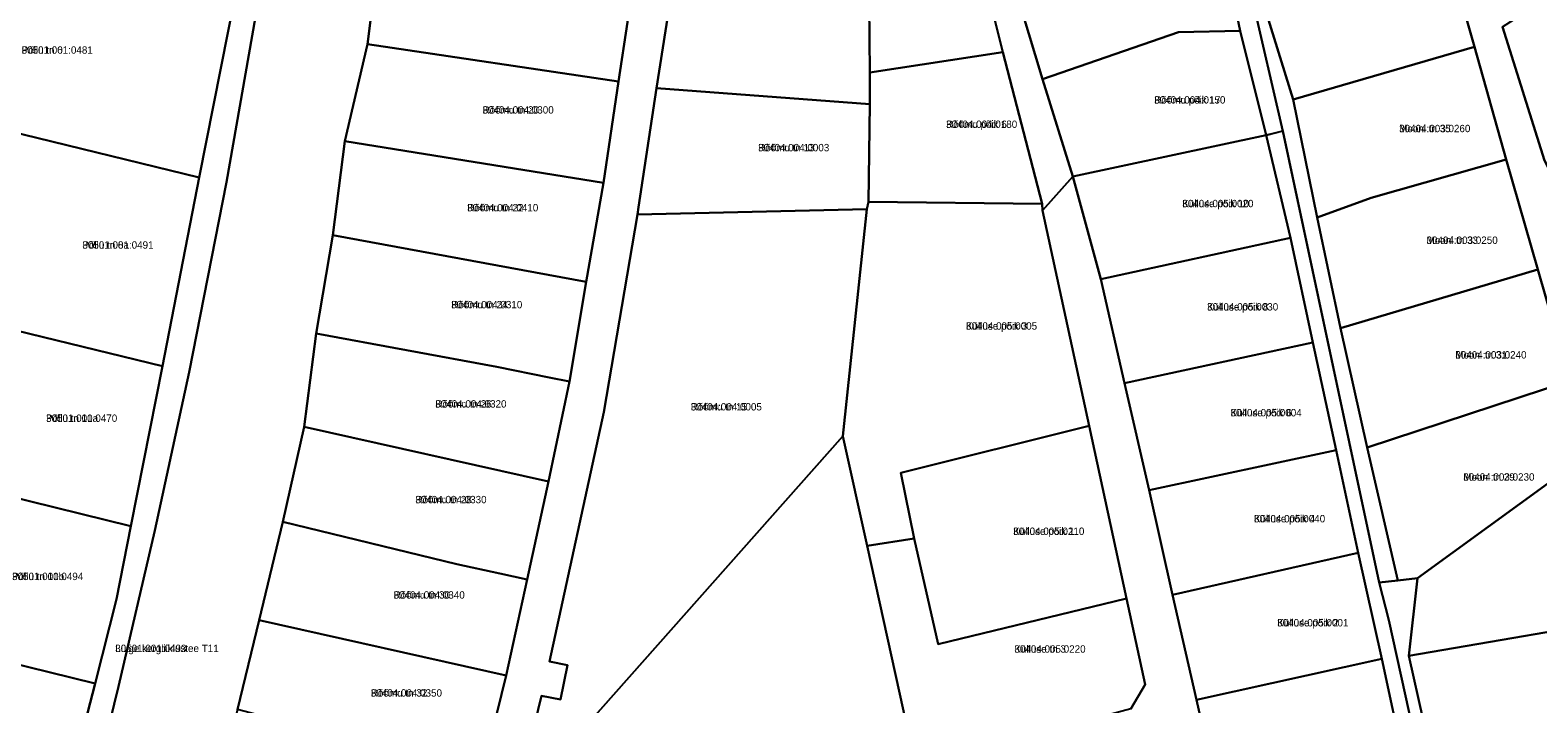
# Model space of a CAD drawing. Extents: x 542681 to 554572, y 6566489 to 6580482.
# Drawn here: x 543956.1 to 544263.2, y 6577115.7 to 6577252.9 of the extents above; entities that cross this region are included whole.
import ezdxf

# ---------------------------------------------------------------- set-up
doc = ezdxf.new("R2010")
doc.units = 0
for name, color, linetype in [('L_AADRESS', 7, 'Continuous'), ('PIIR', 7, 'Continuous'), ('TUNNUS', 7, 'Continuous')]:
    doc.layers.add(name, color=color, linetype=linetype)

msp = doc.modelspace()

# ---------------------------------------------------------------- linework, layer by layer
at = {"layer": 'PIIR'}
for points in [[(543807.92, 6576662.98), (543904.97, 6576885.47), (543907.57, 6576895.31), (543910.99, 6576906.44), (543922.56, 6576941.94), (543936.45, 6576984.61), (543948.61, 6577021.3), (543957.88, 6577054.74), (543966.17, 6577087.14), (543974.03, 6577119.2), (543981.47, 6577151), (543988.44, 6577183.28), (543996.05, 6577221.97), (544002.64, 6577259.57), (544005.96, 6577279.79), (544014.14, 6577348.31), (544016.62, 6577369.15), (544023.92, 6577429.37), (544023.1, 6577434.48), (544025.4, 6577449.01), (544027.21, 6577460.39), (544030.15, 6577550.17)], [(543952.91, 6577055.9), (543961.04, 6577087.76), (543969.28, 6577119.84), (543973.68, 6577136.98), (543976.6, 6577151.88), (543983, 6577184.45), (543990.52, 6577222.87), (543997.84, 6577259.95), (544004.56, 6577302.46), (544005.14, 6577308.18), (544009.28, 6577348.44), (544014.14, 6577348.31), (544005.96, 6577279.79), (544002.64, 6577259.57), (543996.05, 6577221.97), (543988.44, 6577183.28), (543981.47, 6577151), (543974.03, 6577119.2), (543966.17, 6577087.14), (543957.88, 6577054.74), (543948.61, 6577021.3)], [(544343.79, 6577266.92), (544323.61, 6577250.29), (544302.31, 6577236.4), (544281.19, 6577222.69), (544268.33, 6577214.08), (544276.94, 6577176.9), (544280.28, 6577170.48), (544273.95, 6577166.88), (544269.75, 6577181.48), (544263.2, 6577204.14), (544256.79, 6577226.59), (544250.31, 6577249.52), (544239.96, 6577285.6)], [(544152.26, 6577276.33), (544162.33, 6577242.91), (544168.46, 6577223.13), (544162.32, 6577216.19), (544162.21, 6577217.56), (544154.25, 6577248.45), (544146.15, 6577280.82)], [(544088.25, 6577270.53), (544083.69, 6577241.1), (544080.02, 6577216.88), (544079.79, 6577215.37), (544072.96, 6577175.07), (544061.83, 6577124.3), (544065.5, 6577123.55), (544064.08, 6577116.57), (544060.25, 6577117.34), (544054.74, 6577094.79), (544043.36, 6577081.91), (544048.15, 6577101.6), (544053.03, 6577121.49), (544057.31, 6577141.01), (544061.68, 6577160.97), (544065.91, 6577181.35), (544069.36, 6577201.67), (544072.86, 6577221.8), (544075.94, 6577242.44), (544079.61, 6577266.72)], [(544026.68, 6577265.1), (544024.78, 6577250.04), (544020.16, 6577230.32), (544017.69, 6577211.17), (544014.34, 6577191.11), (544011.89, 6577172.09), (544007.52, 6577152.78), (544002.68, 6577132.74), (543998.32, 6577114.57), (543993.36, 6577094.76), (543988.42, 6577075.56), (543983.52, 6577056.39), (543982.26, 6577052.27), (543976.84, 6577032.94), (543971.38, 6577015.47), (543965.45, 6576996.6), (543959.41, 6576977.68), (543956.86, 6576974.93), (543952, 6576959.13)], [(544204.94, 6577259.69), (544211.25, 6577232.37), (544207.86, 6577231.5), (544202.58, 6577252.78), (544201.13, 6577259.66)], [(544207.14, 6577258.94), (544213.36, 6577238.8), (544218.26, 6577214.74), (544223, 6577192.18), (544228.43, 6577167.92), (544234.67, 6577140.84), (544230.87, 6577140.38), (544211.25, 6577232.37), (544204.94, 6577259.69)], [(544256.03, 6577253.6), (544264.6, 6577226.38), (544266.26, 6577223.12), (544269.36, 6577223.2), (544293.74, 6577239.41), (544316.1, 6577253.81)], [(544236, 6577103.69), (544231.41, 6577124.89), (544226.64, 6577146.42), (544222.15, 6577167.37), (544217.35, 6577189.29), (544212.86, 6577210.6), (544207.86, 6577231.5), (544211.25, 6577232.38), (544230.87, 6577140.38), (544232.86, 6577132.75), (544263.5, 6576993.69)], [(544180.29, 6577114.66), (544183.2, 6577119.62), (544179.44, 6577137.12), (544171.81, 6577172.35), (544162.32, 6577216.19), (544168.46, 6577223.13), (544174.21, 6577202.2), (544179.04, 6577181.02), (544184, 6577159.2), (544188.81, 6577137.92), (544193.67, 6577116.5), (544198.52, 6577095.28)], [(544054.74, 6577094.79), (544121.6, 6577170.23), (544126.55, 6577147.86), (544136.48, 6577102.88)], [(544263.5, 6576993.69), (544232.86, 6577132.75), (544230.87, 6577140.38), (544234.67, 6577140.84), (544238.7, 6577141.31), (544236.96, 6577125.44), (544242.8, 6577099.39), (544248.72, 6577072.99), (544253.92, 6577049.8), (544259.33, 6577025.66), (544266.36, 6576994.23)]]:
    msp.add_lwpolyline(points, dxfattribs=at)
for points in [[(544127.01, 6577258.11), (544127.37, 6577286.93), (544146.15, 6577280.82), (544154.25, 6577248.45), (544127.12, 6577244.26)], [(544207.14, 6577258.94), (544239.96, 6577285.6), (544250.31, 6577249.52), (544213.36, 6577238.8)], [(544152.26, 6577276.33), (544201.13, 6577259.66), (544202.58, 6577252.78), (544190.01, 6577252.52), (544162.33, 6577242.91)], [(543915.25, 6577241.33), (543905.31, 6577273.35), (543961.72, 6577265.1), (543997.84, 6577259.95), (543990.52, 6577222.87), (543951.6, 6577232.38), (543945.76, 6577233.79)], [(544088.25, 6577270.53), (544127.01, 6577258.11), (544127.12, 6577244.26), (544127.14, 6577237.81), (544083.69, 6577241.1)], [(544026.68, 6577265.1), (544079.61, 6577266.72), (544075.94, 6577242.44), (544024.78, 6577250.04)], [(544266.26, 6577223.12), (544264.6, 6577226.38), (544256.03, 6577253.6), (544274.81, 6577265.67), (544293.74, 6577239.41), (544269.36, 6577223.2)], [(544162.33, 6577242.91), (544190.01, 6577252.52), (544202.58, 6577252.78), (544207.86, 6577231.5), (544168.46, 6577223.13)], [(544020.16, 6577230.32), (544024.78, 6577250.04), (544075.94, 6577242.44), (544072.86, 6577221.8)], [(544218.26, 6577214.74), (544213.36, 6577238.8), (544250.31, 6577249.52), (544256.79, 6577226.59), (544229.27, 6577218.74)], [(544127.14, 6577237.81), (544127.12, 6577244.26), (544154.25, 6577248.45), (544162.21, 6577217.56), (544126.82, 6577217.97)], [(544083.69, 6577241.1), (544127.14, 6577237.81), (544126.82, 6577217.97), (544126.52, 6577216.45), (544079.79, 6577215.37), (544080.02, 6577216.88)], [(543942.27, 6577194.39), (543951.6, 6577232.38), (543990.52, 6577222.87), (543983, 6577184.45)], [(544168.46, 6577223.13), (544207.86, 6577231.5), (544212.86, 6577210.6), (544174.21, 6577202.2)], [(544072.86, 6577221.8), (544069.36, 6577201.67), (544017.69, 6577211.17), (544020.16, 6577230.32)], [(544218.26, 6577214.74), (544229.27, 6577218.74), (544256.79, 6577226.59), (544263.2, 6577204.14), (544223, 6577192.18)], [(544079.79, 6577215.37), (544126.52, 6577216.45), (544121.6, 6577170.23), (544054.74, 6577094.79), (544060.25, 6577117.34), (544064.08, 6577116.57), (544065.5, 6577123.55), (544061.83, 6577124.3), (544072.96, 6577175.07)], [(544126.82, 6577217.97), (544162.21, 6577217.56), (544162.32, 6577216.19), (544171.81, 6577172.35), (544133.41, 6577162.76), (544136.18, 6577149.35), (544126.55, 6577147.86), (544121.6, 6577170.23), (544126.52, 6577216.45)], [(544017.69, 6577211.17), (544069.36, 6577201.67), (544065.91, 6577181.35), (544061.79, 6577182.18), (544051.13, 6577184.34), (544014.34, 6577191.11)], [(544174.21, 6577202.2), (544212.86, 6577210.6), (544217.35, 6577189.29), (544179.04, 6577181.02)], [(544223, 6577192.18), (544263.2, 6577204.14), (544269.75, 6577181.48), (544228.43, 6577167.92)], [(543935.49, 6577161.97), (543942.27, 6577194.39), (543983, 6577184.45), (543976.6, 6577151.88)], [(544014.34, 6577191.11), (544051.13, 6577184.34), (544061.79, 6577182.18), (544065.91, 6577181.35), (544061.68, 6577160.97), (544011.89, 6577172.09)], [(544179.04, 6577181.02), (544217.35, 6577189.29), (544222.15, 6577167.37), (544184, 6577159.2)], [(544234.67, 6577140.84), (544228.43, 6577167.92), (544269.75, 6577181.48), (544273.95, 6577166.88), (544238.7, 6577141.31)], [(544171.81, 6577172.35), (544179.44, 6577137.12), (544141.07, 6577127.85), (544136.18, 6577149.35), (544133.41, 6577162.76)], [(544011.89, 6577172.09), (544061.68, 6577160.97), (544057.31, 6577141.01), (544051.77, 6577142.22), (544042.97, 6577144.13), (544007.52, 6577152.78)], [(544184, 6577159.2), (544222.15, 6577167.37), (544226.64, 6577146.42), (544188.81, 6577137.92)], [(544238.7, 6577141.31), (544273.95, 6577166.88), (544286.02, 6577133.9), (544236.96, 6577125.44)], [(543927.62, 6577130.07), (543935.49, 6577161.97), (543976.6, 6577151.88), (543973.68, 6577136.98), (543969.28, 6577119.84)], [(544007.52, 6577152.78), (544042.97, 6577144.13), (544051.77, 6577142.22), (544057.31, 6577141.01), (544053.03, 6577121.49), (544002.68, 6577132.74)], [(544136.18, 6577149.35), (544141.07, 6577127.85), (544179.44, 6577137.12), (544183.2, 6577119.62), (544180.29, 6577114.66), (544136.48, 6577102.88), (544126.55, 6577147.86)], [(544188.81, 6577137.92), (544226.64, 6577146.42), (544231.41, 6577124.89), (544193.67, 6577116.5)], [(544018.49, 6577109.27), (543998.32, 6577114.57), (544002.68, 6577132.74), (544053.03, 6577121.49), (544048.15, 6577101.6), (544041.99, 6577103.14), (544036.13, 6577104.63), (544032.11, 6577105.69), (544032.15, 6577105.84), (544018.58, 6577109.61)], [(544236.96, 6577125.44), (544286.02, 6577133.9), (544292.53, 6577118.03), (544285.26, 6577113.83), (544278.03, 6577105.45), (544242.8, 6577099.39)], [(543920.13, 6577097.75), (543927.62, 6577130.07), (543969.28, 6577119.84), (543961.04, 6577087.76)], [(544193.67, 6577116.5), (544231.41, 6577124.89), (544236, 6577103.69), (544198.52, 6577095.28)]]:
    msp.add_lwpolyline(points, close=True, dxfattribs=at)

# ---------------------------------------------------------------- texts
at = {"layer": 'L_AADRESS'}
for s, p in [('Põllu tn 6', (543954.32, 6577248.11)), ('Rõõmu tn 20', (544048.22, 6577235.92)), ('Rõõmu põik 17', (544185.06, 6577237.96)), ('Rõõmu põik 6', (544142.65, 6577233)), ('Mooni tn 35', (544234.97, 6577232.13)), ('Rõõmu tn 13', (544104.36, 6577228.24)), ('Külluse põik 10', (544190.78, 6577216.85)), ('Rõõmu tn 22', (544045.08, 6577216)), ('Põllu tn 8a', (543966.7, 6577208.41)), ('Mooni tn 33', (544240.54, 6577209.38)), ('Rõõmu tn 24', (544041.82, 6577196.26)), ('Külluse põik 8', (544195.82, 6577195.81)), ('Külluse põik 3', (544146.71, 6577191.91)), ('Mooni tn 31', (544246.41, 6577186.03)), ('Rõõmu tn 26', (544038.6, 6577176.04)), ('Rõõmu tn 15', (544090.63, 6577175.45)), ('Külluse põik 6', (544200.61, 6577174.24)), ('Põllu tn 10a', (543959.3, 6577173.13)), ('Mooni tn 29', (544248.03, 6577161.16)), ('Rõõmu tn 28', (544034.54, 6577156.55)), ('Külluse põik 4', (544205.39, 6577152.65)), ('Külluse põik 1', (544156.33, 6577150.1)), ('Põllu tn 10b', (543952.37, 6577140.9)), ('Rõõmu tn 30', (544030.1, 6577137.13)), ('Külluse põik 2', (544210.12, 6577131.46)), ('Luige kergliiklustee T11', (543973.39, 6577126.24)), ('Külluse tn 3', (544156.58, 6577126.12)), ('Rõõmu tn 32', (544025.46, 6577117.17))]:
    msp.add_text(s, height=1.5, dxfattribs=at).set_placement(p)
at = {"layer": 'TUNNUS'}
for s, p in [('30501:001:0481', (543954.32, 6577248.11)), ('30404:004:0300', (544048.22, 6577235.92)), ('30404:004:0150', (544185.06, 6577237.96)), ('30404:004:0180', (544142.65, 6577233)), ('30404:003:0260', (544234.97, 6577232.13)), ('30404:004:0003', (544104.36, 6577228.24)), ('30404:005:0020', (544190.78, 6577216.85)), ('30404:004:0410', (544045.08, 6577216)), ('30501:001:0491', (543966.7, 6577208.41)), ('30404:003:0250', (544240.54, 6577209.38)), ('30404:004:0310', (544041.82, 6577196.26)), ('30404:005:0030', (544195.82, 6577195.81)), ('30404:005:0005', (544146.71, 6577191.91)), ('30404:003:0240', (544246.41, 6577186.03)), ('30404:004:0320', (544038.6, 6577176.04)), ('30404:004:0005', (544090.63, 6577175.45)), ('30404:005:0004', (544200.61, 6577174.24)), ('30501:001:0470', (543959.3, 6577173.13)), ('30404:003:0230', (544248.03, 6577161.16)), ('30404:004:0330', (544034.54, 6577156.55)), ('30404:005:0040', (544205.39, 6577152.65)), ('30404:005:0210', (544156.33, 6577150.1)), ('30501:001:0494', (543952.37, 6577140.9)), ('30404:004:0340', (544030.1, 6577137.13)), ('30404:005:0001', (544210.12, 6577131.46)), ('30501:001:0493', (543973.39, 6577126.24)), ('30404:005:0220', (544156.58, 6577126.12)), ('30404:004:0350', (544025.46, 6577117.17))]:
    msp.add_text(s, height=1.5, dxfattribs=at).set_placement(p)

doc.saveas('drawing.dxf')
